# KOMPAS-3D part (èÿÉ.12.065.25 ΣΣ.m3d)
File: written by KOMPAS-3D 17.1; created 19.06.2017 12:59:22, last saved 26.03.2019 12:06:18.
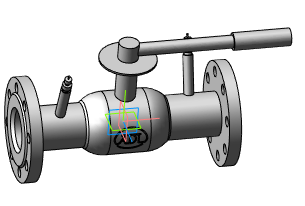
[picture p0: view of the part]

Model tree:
1. Операция без истории:2  (labels: Сталь 20  ГОСТ 1050-88)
